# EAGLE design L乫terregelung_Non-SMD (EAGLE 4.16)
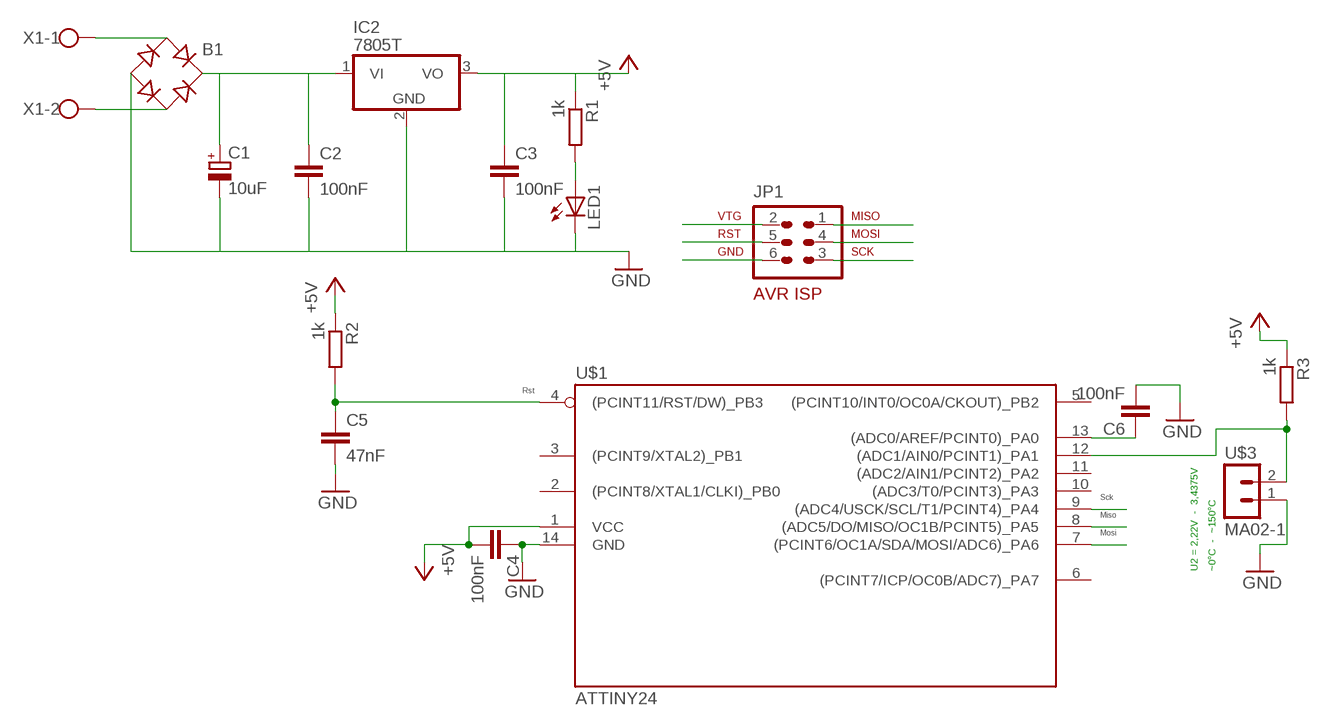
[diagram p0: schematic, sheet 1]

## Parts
B1  B-DIL  [B-DIL]
C1  10uF  CPOL-EUE2.5-6  [E2,5-6]
C2  100nF  C-EU025-024X044  [C025-024X044]
C3  100nF  C-EU025-024X044  [C025-024X044]
C4  100nF  C-EU025-024X044  [C025-024X044]
C5  47nF  C-EU025-024X044  [C025-024X044]
C6  100nF  C-EU025-024X044  [C025-024X044]
IC2  7805T  [TO220H]
JP1  AVR-ISP-6  [AVR-ISP-6]
LED1  LED5MM  [LED5MM]
R1  1k  R-EU_0204/7  [0204/7]
R2  1k  R-EU_0204/7  [0204/7]
R3  1k  R-EU_0204/7  [0204/7]
U$1  ATTINY24  [DIL14]
U$3  MA02-1  [MA02-1]
X1  W237-102  [W237-102]

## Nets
+5V: C3.1 C4.2 IC2.3(VO) JP1.2 R1.1 R2.1 R3.1 U$1.1(VCC)
GND: B1.- C1.- C2.2 C3.2 C4.1 C5.2 C6.2 IC2.2(GND) JP1.6 LED1.K(C) U$1.14(GND) U$3.1
MISO: JP1.1 U$1.8((ADC5/DO/MISO/OC1B/PCINT5)_PA5)
MOSI: JP1.4 U$1.7((PCINT6/OC1A/SDA/MOSI/ADC6)_PA6)
N$1: B1.AC1 X1.1
N$2: B1.+ C1.+ C2.1 IC2.1(VI)
N$3: C6.1 U$1.13((ADC0/AREF/PCINT0)_PA0)
N$4: LED1.A R1.2
N$5: B1.AC2 X1.2
N$6: R3.2 U$1.12((ADC1/AIN0/PCINT1)_PA1) U$3.2
RST: C5.1 JP1.5 R2.2 U$1.4((PCINT11/RST/DW)_PB3)
SCK: JP1.3 U$1.9((ADC4/USCK/SCL/T1/PCINT4)_PA4)
Unconnected: U$1.2((PCINT8/XTAL1/CLKI)_PB0) U$1.3((PCINT9/XTAL2)_PB1) U$1.5((PCINT10/INT0/OC0A/CKOUT)_PB2) U$1.6((PCINT7/ICP/OC0B/ADC7)_PA7) U$1.10((ADC3/T0/PCINT3)_PA3) U$1.11((ADC2/AIN1/PCINT2)_PA2)

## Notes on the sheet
- Rst
- Sck
- Miso
- Mosi
- U2 = 2,22V  -  3,4375V | ~0°C  -  ~150°C

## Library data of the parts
B1 = rectifier:B-DIL: RECTIFIER
C1 = rcl:CPOL-EU: POLARIZED CAPACITOR, European symbol
C2-C6 = rcl:C-EU: CAPACITOR, European symbol
IC2 = linear:78*: Positive VOLTAGE REGULATOR Source: http://cache.national.com/ds/LM/LM78L05.pdf http://www.fairchildsemi.com/ds/LM/LM7805.pdf
JP1 = atmel-1:AVR-ISP-6: AVR ISP-6 Serial Programming Header
LED1 = led:LED: LED
R1-R3 = rcl:R-EU_: RESISTOR, European symbol
U$1 = Steffi2:ATTINY24
U$3 = con-lstb:MA02-1
X1 = con-wago-500:W237-102: WAGO SCREW CLAMP

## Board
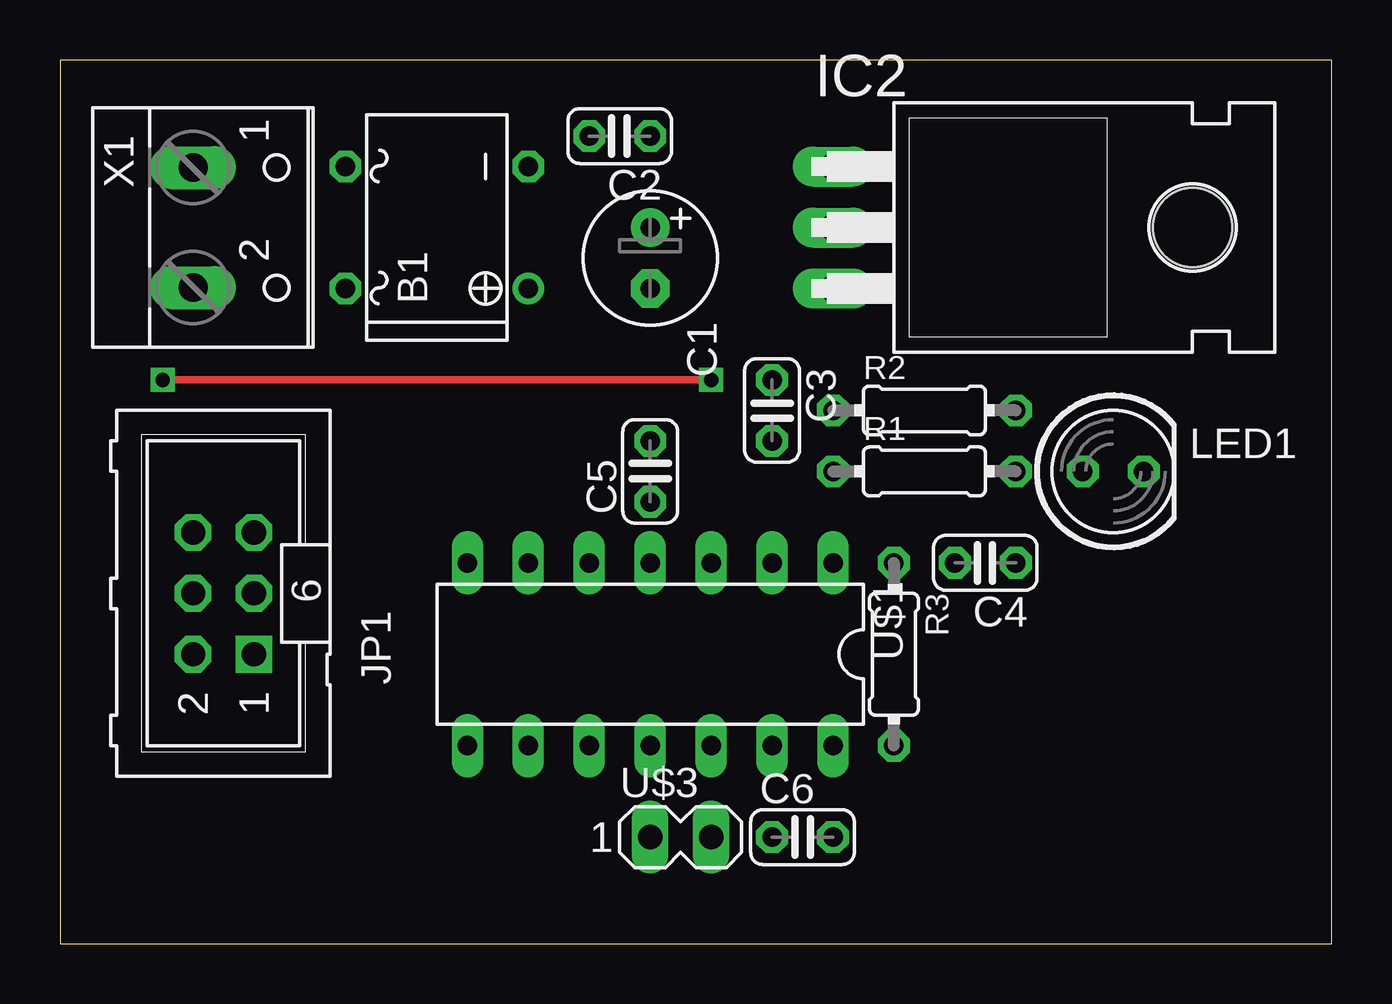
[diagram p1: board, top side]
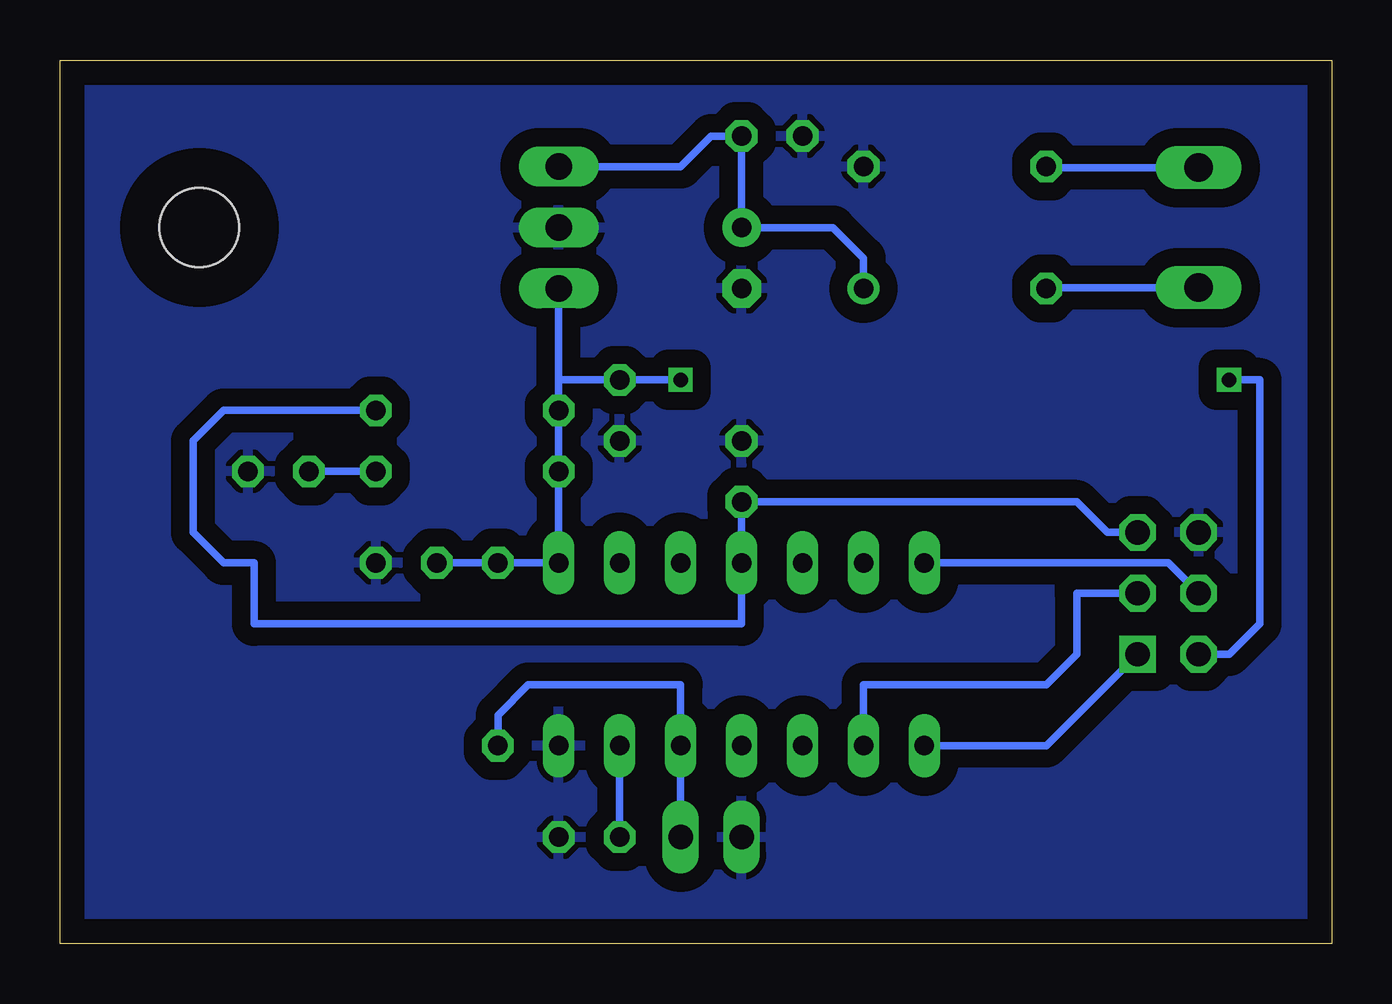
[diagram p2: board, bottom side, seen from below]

Size 53.01 x 36.82 mm. Coordinates in mm from the lower left corner, seen from the top.
Outline: 0,0 53.01,0 53.01,36.82 0,36.82 0,0
Copper layers (1*16): Top 0.035mm / dielectric 1.5mm / Bottom 0.035mm
Design rules "default": minimum track width 10mil, minimum drill 24mil, track to track 8mil, track to pad 8mil, pad to pad 8mil, via to via 8mil, smd to smd 8mil, copper to edge 40mil, drill to drill 8mil, minimum pad ring 10mil, minimum via ring 8mil, stop-mask expansion 4mil, vias tented up to drill 0mil, thermal gap 10mil

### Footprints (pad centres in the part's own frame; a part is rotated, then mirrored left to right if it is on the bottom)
B-DIL = drill 0.813 round: + -2.54,-3.81 | drill 0.813 octagon: - 2.54,-3.81; AC1 2.54,3.81; AC2 -2.54,3.81
E2,5-6 = drill 0.813 pad 1.6 round: + -1.27,0 | drill 0.813 pad 1.6 octagon: - 1.27,0
C025-024X044 = drill 0.813 octagon: 1 -1.27,0; 2 1.27,0
TO220H = drill 1.118 long: 1 -2.54,-10.16; 2 0,-10.16; 3 2.54,-10.16 | hole 3.302: 0,4.826
AVR-ISP-6 = drill 1.016 square: 1 -2.54,-1.27 | drill 1.016 octagon: 2 -2.54,1.27; 3 0,-1.27; 4 0,1.27; 5 2.54,-1.27; 6 2.54,1.27
LED5MM = drill 0.813 octagon: A -1.27,0; K 1.27,0
0204/7 = drill 0.813 octagon: 1 -3.81,0; 2 3.81,0
DIL14 = drill 0.813 long: 1 -5.08,-3.81; 2 -2.54,-3.81; 3 0,-3.81; 4 2.54,-3.81; 5 5.08,-3.81; 6 7.62,-3.81; 7 10.16,-3.81; 8 10.16,3.81; 9 7.62,3.81; 10 5.08,3.81; 11 2.54,3.81; 12 0,3.81; 13 -2.54,3.81; 14 -5.08,3.81
MA02-1 = drill 1.016 long: 1 -1.27,0; 2 1.27,0
W237-102 = drill 1.194 long: 1 -2.5,-1.27; 2 2.5,-1.27

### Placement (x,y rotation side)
B1  15.71,29.84 90 top
C1  24.6,28.57 270 top
C2  23.33,33.65 180 top
C3  29.68,22.22 270 top
C4  38.57,15.87 180 top
C5  24.6,19.68 90 top
C6  30.95,4.44 0 top
IC2  42.38,29.84 270 top
JP1  6.82,14.6 90 top
LED1  43.9,19.68 0 top
R1  36.03,19.68 0 top
R2  36.03,22.22 0 top
R3  34.76,12.06 270 top
U$1  27.14,12.06 180 top
U$3  25.87,4.44 0 top
X1  6.82,29.84 270 top

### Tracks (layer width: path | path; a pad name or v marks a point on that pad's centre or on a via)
+5V  (via drill 0.6)
  Top 0.305: v4.28,23.49 v27.14,23.49
  Bottom 0.305: R3.1 C4.2 U$1.1 R1.1 R2.1 | R2.1 IC2.3 | R2.1 32.22,23.49 C3.1 v27.14,23.49 | JP1.2 4.28,12.06 3.01,13.33 3.01,23.49 v4.28,23.49
GND
  pour Bottom (isolate 0.762): -0.8,37.46 53.81,37.46 53.81,-0.64 -0.8,-0.64
MISO
  Bottom 0.305: JP1.1 11.9,8.25 U$1.8
MOSI
  Bottom 0.305: JP1.4 6.82,15.87 U$1.7
N$1
  Bottom 0.305: X1.1 11.86,32.34 B1.AC1
N$2
  Bottom 0.305: B1.+ 19.52,28.57 20.79,29.84 C1.+ C2.1 25.87,33.65 27.14,32.38 IC2.1
N$3
  Bottom 0.305: C6.1 U$1.13
N$4
  Bottom 0.305: R1.2 LED1.A
N$5
  Bottom 0.305: X1.2 11.86,27.34 B1.AC2
N$6
  Bottom 0.305: R3.2 34.76,9.52 33.49,10.79 27.14,10.79 U$1.12 U$3.2
RST
  Bottom 0.305: R2.2 46.19,22.22 47.46,20.95 47.46,17.14 46.19,15.87 44.92,15.87 44.92,13.33 24.6,13.33 U$1.4 C5.1 10.63,18.41 9.36,17.14 JP1.5
SCK
  Bottom 0.305: JP1.3 10.63,14.6 10.63,12.06 11.9,10.79 19.52,10.79 U$1.9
